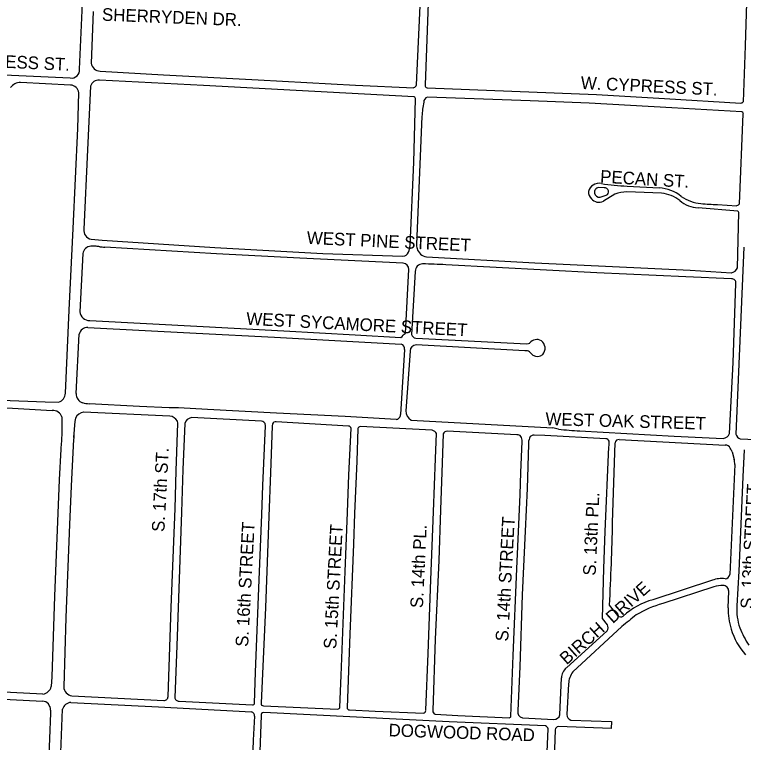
# Model space of a CAD drawing. Extents: x 0 to 712119, y 0 to 761125.
# Drawn here: x 680612 to 683499, y 731141 to 734022 of the extents above; entities that cross this region are included whole.
import ezdxf

# ---------------------------------------------------------------- set-up
doc = ezdxf.new("R2010")
doc.units = 0
doc.layers.add('PAVED ROADS', color=7, linetype='Continuous')
doc.layers.add('street names', color=7, linetype='Continuous')

msp = doc.modelspace()

# ---------------------------------------------------------------- linework, layer by layer
at = {"layer": 'PAVED ROADS'}
for points in [[(680869.7, 733805.7), (680883.3, 734126.3), (680904.1, 734493.2), (680918.9, 734762.7)], [(682204.7, 733744.2), (682229.7, 734285.1)], [(682257.9, 734284.2), (682238.1, 733743.1)], [(683499.5, 733677.1), (683508, 733897.5), (683513.4, 734067.8), (683517, 734202)], [(680922.7, 734033.9), (680915.2, 733829.3)], [(680309.5, 733795), (680832.7, 733771.1)], [(680950.8, 733798.1), (681202.6, 733783.9), (681576.6, 733764.1), (681963.1, 733742.7), (682194, 733732.5)], [(682195.2, 733695.7), (681728.1, 733721.1), (681360.2, 733740.9), (680947.9, 733762.4)], [(680833.9, 733743), (680635.6, 733753.5)], [(680912.6, 733738.3), (680900.3, 733485.9), (680886.2, 733172.6)], [(680813.1, 732523.2), (680828.2, 732852.3), (680843.8, 733174.4), (680862.2, 733570.6), (680866.4, 733712.5)], [(682246.2, 733731.6), (682917.1, 733705.1), (683186.6, 733689.1), (683489.5, 733671.4)], [(682174.8, 733087.6), (682179, 733107.9), (682193.5, 733437), (682200.7, 733687)], [(683492.6, 733637.2), (683215.4, 733652.8), (682888.3, 733671.7), (682654.1, 733680.1), (682247.9, 733694.3)], [(682225.7, 733619), (682204.1, 733113.2)], [(683484.4, 733273.2), (683499.1, 733629.5)], [(682947.7, 733336.1), (682925.5, 733336.8)], [(683038.6, 733343.1), (683165.8, 733335.6)], [(682932.5, 733299.5), (682955.8, 733306.5)], [(682990.5, 733310.5), (682944.9, 733282.9)], [(683175.1, 733315.2), (683037.9, 733319.9)], [(683477.7, 733243.7), (683320, 733256.9)], [(683396.6, 733270.1), (683473.9, 733265.4)], [(683475.9, 733019.4), (683481.2, 733238)], [(680915.6, 733132.6), (680958.5, 733128.2), (681405.6, 733100), (681833.7, 733076.7), (682148.7, 733065.4), (682157.5, 733066.6)], [(680934.7, 733104.7), (680914.1, 733105.2)], [(682151.8, 733038.2), (681742.2, 733057.4), (681411.6, 733075.1), (680969.1, 733101.1)], [(683501.3, 733101.4), (683469.2, 732361.3)], [(680882.8, 733075.7), (680870.8, 732845.2), (680870.8, 732845.2)], [(682244, 733062.9), (682673.5, 733039.7), (683288.2, 733009.6), (683451.6, 732999.7)], [(682160.2, 732761), (682174.5, 733012.5)], [(683452.2, 732975.3), (683271.4, 732983.1), (682918.9, 732998.9), (682320.6, 733031.1)], [(682199.3, 733005.3), (682185, 732755.7)], [(683444.4, 732363.2), (683458.5, 732645.1), (683469.6, 732957.9)], [(680910.1, 732810.7), (681359.7, 732786.9), (681678.8, 732769.4), (681961.8, 732754.4), (682142.4, 732743.6)], [(680902.8, 732783.1), (681331.1, 732761.3), (681641.1, 732745.4), (682144.1, 732717.3)], [(680856.3, 732521.3), (680868.1, 732757.1)], [(682201, 732740.6), (682641.9, 732718.4)], [(682156.5, 732696.3), (682140.5, 732438.3)], [(682634.1, 732690.9), (682202.4, 732714.6)], [(682178.8, 732690.1), (682162.5, 732453.4)], [(680559.8, 732496), (680733.1, 732489.4), (680786.2, 732488.2)], [(680087.9, 732489.7), (680226.2, 732482.5), (680512, 732469.6), (680761, 732455)], [(681224.2, 732465.4), (681107.1, 732470.4), (680907.8, 732480.9)], [(682123.4, 732419.2), (681921.8, 732430.5), (681649.7, 732443.6), (681376.3, 732458.7), (681262, 732464.8)], [(681226.8, 732432.8), (680885.7, 732447.9)], [(680799.8, 732429.1), (680799.4, 732363.7)], [(680853.7, 732423.8), (680850.8, 732411.6), (680848.3, 732380.6)], [(681219.9, 731322), (681232.6, 731674.5), (681247.8, 732066.9), (681252.6, 732215.1), (681258.8, 732404.7), (681257.1, 732412.4)], [(681590.8, 732412.2), (681312.5, 732426.4)], [(681935, 732393.2), (681648.6, 732409.2)], [(682123.4, 732419.2), (682123.4, 732419.2)], [(682183, 732416.6), (682743.9, 732386.4)], [(681286.4, 732403.7), (681279, 732221), (681273.9, 732052.7), (681254.6, 731523), (681247.3, 731319.1), (681247.3, 731319.1), (681247.3, 731319.1)], [(681562.9, 731296.5), (681567.1, 731418.3), (681581.4, 731784), (681592, 732043.2), (681595.9, 732157.5), (681605.7, 732394.4), (681604.8, 732402.6)], [(681634.1, 732401.2), (681633.1, 732392.6), (681625.9, 732208.7), (681619, 732035.5), (681605.5, 731675.1), (681589.2, 731296.2), (681589.2, 731296.2), (681589.2, 731296.2)], [(681901.2, 731280.6), (681906.3, 731405.5), (681921.5, 731817.2), (681930.7, 732051.3), (681936.6, 732199.9), (681945.3, 732383.4)], [(681972, 732382.9), (681968.4, 732254.1), (681959.3, 732046.2), (681954.3, 731925.8), (681940.7, 731569.5), (681929.3, 731278.5)], [(682266.7, 732376.3), (681981.1, 732390.7)], [(680846.9, 732355.3), (680846.3, 732348), (680846.9, 732355.3)], [(682241.6, 731267.7), (682250.4, 731492.7), (682261.2, 731784.1), (682271.2, 732053.6), (682279.5, 732264.1), (682283.4, 732363.1)], [(682310.1, 732362.5), (682305.9, 732247.6), (682299.1, 732061.7), (682292.2, 731861.1), (682278.2, 731549.1), (682269.5, 731266.6)], [(682602.1, 732358.7), (682325.4, 732373.2)], [(682954.3, 732342.6), (682713.1, 732355.2), (682670.8, 732356.9)], [(682850.7, 732373.5), (683225.1, 732352.7), (683419.6, 732344)], [(680846, 732340.7), (680835.7, 732155.7), (680829.7, 732003.6), (680815.1, 731634.7), (680806.9, 731360.1)], [(682578, 731244.7), (682586.9, 731484.5), (682602.3, 731828.2), (682614.9, 732121.7), (682618, 732209.5), (682622.5, 732331.7)], [(682647.5, 732321.3), (682642.2, 732145.3), (682634.3, 731976.5), (682623.5, 731725.1), (682613.1, 731440.5), (682605.5, 731266.4)], [(682981.4, 732011.8), (682991.8, 732326.9)], [(683007.1, 732339.5), (683427.7, 732316.9)], [(683486.7, 732342.1), (683908.7, 732323.8)], [(680795.5, 732301), (680789.1, 732180.6), (680770.4, 731719.2), (680759, 731400.9), (680757.1, 731361.9)], [(682960.4, 731606.3), (682941.4, 731631.6), (682946.6, 731829.2), (682952.3, 731975.2), (682966.6, 732310.7)], [(683455.3, 732290.9), (683462.7, 732261.2)], [(683502.3, 732299.2), (683497.7, 732191.9), (683480.8, 731819.1), (683473.4, 731681)], [(683465.5, 732241.2), (683445.3, 731805.3)], [(683376.9, 731782.8), (683141.2, 731705.4)], [(683382.4, 731756.9), (683179.8, 731690.1)], [(683438.8, 731673), (683441.3, 731738.8)], [(683001.5, 731642.8), (682969.4, 731684.6)], [(683017.9, 731599), (682824.2, 731419.6)], [(682797.9, 731436), (682959, 731581.8)], [(682772.6, 731249.9), (682778.7, 731396)], [(682806.8, 731372.7), (682800.2, 731250.9)], [(680723.9, 731332), (680466.5, 731345), (680363, 731349)], [(680362, 731322), (680722.5, 731303.9)], [(680839.2, 731325.5), (681203.2, 731306.3)], [(680834.7, 731298.9), (681182.6, 731281.3), (681550, 731261.5)], [(681263.5, 731304.2), (681554.3, 731288.9)], [(681597.5, 731285.6), (681891.5, 731272.6)], [(680754.3, 731268.5), (680754, 731256.5), (680745.9, 731055.8), (680733.8, 730743), (680722.2, 730457.2), (680708.9, 730130.9), (680699.4, 729867.4)], [(680792.9, 731031.8), (680802.4, 731271.8), (680802.4, 731271.8)], [(682715.6, 731206.2), (682334, 731222), (681599.2, 731259)], [(681939, 731270.2), (682040.8, 731264.4), (682231.5, 731256.3)], [(682278.7, 731251.9), (682368.1, 731246.7), (682572.2, 731238.5)], [(681562.3, 731244), (681557.7, 731149.9), (681551.8, 730992.9)], [(681588.3, 731246.8), (681579.3, 730998.3)], [(682624, 731237.5), (682748, 731231.5)], [(682815.6, 731229.3), (682976.4, 731223.4), (682976, 731195.2), (682766.3, 731203.4)], [(682753, 731190.3), (682750.7, 731114.5), (682737.2, 730828.1), (682732.7, 730724.5), (682705.1, 730727.6), (682717.1, 730980.9), (682725.8, 731193.8)]]:
    msp.add_lwpolyline(points, dxfattribs=at)
for centre, radius, start, end in [((680951.7, 733834.9), 36.8, 188.7831, 268.6367), ((680837.8, 733802.8), 32.1, 260.9447, 5.2465), ((680945, 733728.8), 33.7, 84.9664, 163.6847), ((680636.1, 733704.8), 48.7, 90.4893, 144.9975), ((680832.4, 733708.9), 34.2, 5.9649, 87.4851), ((682188.8, 733748.1), 16.4, 288.4137, 346.4081), ((682247.2, 733740.9), 9.39, 166.9959, 264.0021), ((682192.6, 733688), 8.17, 352.9804, 71.8473), ((682253, 733674.7), 20.3, 104.577, 178.6761), ((683488.3, 733684.8), 13.5, 274.8931, 325.2519), ((682622.9, 733598.2), 397.7, 168.8469, 176.9972), ((683490.3, 733628.6), 8.88, 5.7732, 74.9625), ((682918.6, 733317.7), 32.8, 117.1401, 228.8806), ((682926.6, 733314.2), 39.9, 74.8646, 125.0308), ((682927.4, 733318.7), 18.2, 95.9518, 190.2663), ((683054.6, 734057.7), 714.8, 260.5333, 268.7231), ((682949.8, 733320.7), 15.5, 292.7557, 97.7775), ((683156.7, 733180.8), 155.1, 51.5905, 86.6374), ((682929.1, 733319.2), 20, 190.8543, 279.8128), ((683038.4, 733192.9), 127, 90.2111, 112.1611), ((683157.4, 733167.9), 148.4, 52.3752, 83.1333), ((683343.1, 733429.8), 156.1, 234.7593, 265.5824), ((682927.6, 733319.2), 40.2, 220.7056, 295.5885), ((683323.3, 733370.3), 113.5, 228.4111, 268.367), ((683402.6, 733895.6), 625.5, 263.4365, 269.448), ((683444, 733317.5), 60, 299.8696, 312.3911), ((683476.1, 733238.8), 5.14, 351.1006, 72.1998), ((680922.6, 733168.5), 36.7, 173.7067, 258.9723), ((680917.4, 733070.3), 35.1, 95.4018, 171.0736), ((680925.7, 732967.2), 137.7, 79.7856, 86.233), ((681445, 738666.1), 5585.3, 264.9171, 265.1125), ((682245.8, 733111.1), 41.7, 177.1228, 201.0537), ((682147.3, 733092.7), 28, 291.5433, 349.5289), ((682248.4, 733105.2), 42.5, 192.317, 264.1112), ((682146.8, 733010.9), 27.7, 3.2857, 79.7579), ((682228.2, 733005.7), 28.9, 90.2796, 180.8439), ((682217.9, 731562), 1472.7, 85.9979, 89.602), ((683446.6, 733030.6), 31.3, 279.0502, 339.0541), ((683454.7, 732960.4), 15.1, 350.6017, 99.4285), ((680909.5, 732849.7), 39.1, 186.6474, 270.7747), ((680900.6, 732749.8), 33.3, 86.3016, 167.3425), ((681768.8, 733144.9), 548.2, 312.9536, 315.5604), ((682206, 732761.9), 21.9, 196.5895, 256.9636), ((682681.4, 732698.9), 36.6, 60.8219, 141.8753), ((682676.4, 732701.4), 37.3, 318.9618, 52.1769), ((682136.8, 732698.9), 19.8, 352.4889, 68.4853), ((682203.7, 732689.7), 25, 93.1651, 178.9153), ((682642.8, 732735.7), 17.2, 266.9393, 304.9218), ((682638.5, 732667.2), 24.1, 55.5682, 100.5223), ((682786.1, 732800.5), 175.5, 220.2439, 226.5278), ((682682.3, 732702.4), 33.9, 240.0202, 311.0231), ((680777.6, 732522.7), 35.6, 284.09, 0.7562), ((680889.9, 732518.2), 33.7, 174.7104, 255.4428), ((680935.8, 732713.4), 234.2, 256.5759, 263.1476), ((681233.5, 731810.3), 655.2, 87.507, 90.8195), ((680762.8, 732415.8), 39.2, 19.8948, 92.7413), ((680887.8, 732411.9), 36.1, 93.2988, 160.8576), ((682123.1, 732436.7), 17.5, 271.2513, 5.2711), ((682205.8, 732453.4), 43.3, 179.9075, 238.1184), ((681221.5, 732392.2), 40.9, 29.5843, 82.6004), ((681318.3, 732393.3), 33.5, 99.8762, 162.0522), ((681588.3, 732393.4), 18.9, 29.0601, 82.47), ((681645.4, 732397.8), 11.8, 74.5873, 163.1582), ((681163.2, 732349.9), 316.4, 174.4477, 179.0333), ((681933.3, 732381.1), 12.2, 11.1249, 82.4051), ((681981.6, 732381), 9.75, 92.9927, 168.4473), ((682567.6, 731622.3), 784.1, 75.3122, 77.0095), ((682912.2, 733577.6), 1205.6, 263.0558, 267.0794), ((683809.2, 732144.2), 3017.8, 175.8279, 177.0211), ((681053.1, 732336), 207.1, 174.6704, 178.6966), ((682261.5, 732352.6), 24.3, 25.5128, 77.7239), ((682327.8, 732353.5), 19.8, 96.7855, 152.7886), ((682603.4, 732340.5), 18.3, 39.3101, 93.9698), ((682592, 732335.1), 30.7, 353.6955, 33.6339), ((682667.6, 732340.9), 16.3, 78.6569, 163.0052), ((683416.7, 732373.4), 29.6, 275.7219, 339.7444), ((683496.5, 732368.7), 28.3, 195.1626, 249.8702), ((682711.7, 732321.9), 64.2, 158.2542, 180.5654), ((682954.8, 732329.8), 12.7, 16.1984, 92.3032), ((682856.4, 732324.3), 111, 353.0038, 4.7146), ((683005.4, 732325.9), 13.7, 82.8473, 175.6002), ((683430.3, 732299), 18.1, 19.8452, 98.2309), ((683023.8, 732057.9), 490.4, 28.3673, 30.2763), ((683388.1, 732240.5), 77.4, 0.4693, 15.5321), ((666675, 732447.8), 16312.2, 357.31839, 358.46831), ((683427, 731807), 18.4, 268.4804, 354.6732), ((683414, 731681.9), 107.5, 83.2931, 110.2041), ((683422.5, 731595.5), 166.3, 91.3601, 103.9608), ((683419.2, 731739.7), 22.1, 357.7036, 91.5124), ((683213.7, 731434.5), 280.4, 104.974, 132.7133), ((683271.4, 731330.1), 371.4, 104.272, 121.8956), ((683684, 731665.2), 245.3, 178.1739, 198.0365), ((683712, 731668.1), 238.9, 176.9188, 198.1079), ((683013.8, 731655), 17.3, 224.6336, 303.7488), ((684087.1, 730340.9), 1651.1, 127.8007, 130.358), ((682941.5, 731595.1), 22, 322.807, 30.6449), ((683721.7, 731674.2), 284, 197.4037, 221.0618), ((683969.4, 731800.7), 526.8, 203.1195, 211.5298), ((682835, 731393.6), 56.4, 131.1751, 177.5825), ((682884.9, 731370.4), 78.2, 140.9945, 178.267), ((680719.6, 731370.1), 38.4, 276.5122, 347.5903), ((680843.1, 731361.6), 36.3, 182.3863, 263.8415), ((681203.9, 731322.3), 16, 267.7377, 358.7934), ((681261.7, 731318.5), 14.4, 177.6698, 277.2065), ((680720.9, 731270.5), 33.4, 356.5431, 87.3526), ((680837.3, 731263), 36, 94.0858, 165.8591), ((681553.8, 731298.2), 9.3, 273.2718, 349.5747), ((681597.1, 731293.8), 8.27, 163.5102, 272.7851), ((681891.7, 731282.2), 9.64, 269.1535, 350.3605), ((681547.5, 731246.6), 15.1, 349.9592, 80.484), ((681598.6, 731248.6), 10.4, 86.246, 189.8709), ((681937.1, 731277.9), 7.89, 175.1785, 283.3479), ((682228.7, 731269), 13, 282.3587, 354.1085), ((682281.8, 731264.1), 12.6, 168.7859, 255.7735), ((682630.2, 731261.8), 25.1, 169.5329, 255.6084), ((682821, 731249.4), 20.8, 175.9712, 254.9316), ((682572.4, 731244.1), 5.57, 267.9335, 7.0579), ((682747.6, 731257.6), 26.2, 270.8616, 342.8516), ((682710.1, 731191.3), 15.9, 9.1397, 69.6581), ((682768.8, 731187.7), 15.9, 98.6912, 170.3319)]:
    msp.add_arc(centre, radius, start, end, dxfattribs=at)

# ---------------------------------------------------------------- texts
at = {"layer": 'street names'}
for s, rotation, p in [('SHERRYDEN DR.', 357.7244, (680957.5, 733997.9)), ('W. CYPRESS ST.', 357.2088, (680288.3, 733825.3)), ('W. CYPRESS ST.', 357.2088, (682854.2, 733727.5)), ('PECAN ST.', 356.59, (682930.8, 733356.7)), ('WEST PINE STREET', 357.3474, (681768.8, 733114.1)), ('WEST SYCAMORE STREET', 357.0105, (681529, 732794)), ('WEST OAK STREET', 358.3605, (682714.7, 732396.9)), ('S. 17th ST.', 86.9341, (681205.4, 731973)), ('S. 13th STREET', 86.9341, (683537.3, 731668.5)), ('S. 13th PL.', 87.3457, (682913.8, 731799.9)), ('S. 14th STREET', 86.9341, (682567.4, 731539.5)), ('S. 16th STREET', 86.9341, (681537.1, 731518.3)), ('S. 15th STREET', 86.9341, (681886.2, 731509.6)), ('S. 14th PL.', 87.3457, (682229.6, 731671.7)), ('BIRCH  DRIVE', 41.8114, (682799.1, 731445.4)), ('DOGWOOD ROAD', 358.0379, (682093.1, 731164.8))]:
    msp.add_text(s, height=50, rotation=rotation, dxfattribs=at).set_placement(p)

doc.saveas('drawing.dxf')
